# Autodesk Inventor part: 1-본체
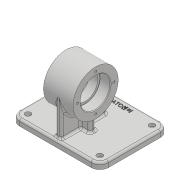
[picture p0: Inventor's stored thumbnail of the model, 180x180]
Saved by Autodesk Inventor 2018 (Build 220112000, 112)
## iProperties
Created: 2019-09
Part Number: 1-본체
Material: 일반
Document SubType Name: Modeling
Designer: USER
Density: 1 g/cm^3
Appearance: 기본값
Author: USER
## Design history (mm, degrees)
sketch "스케치1"
  geometry: L1 (-63, -49)-(63, -49); L2 (63, -49)-(63, 49); L3 (63, 49)-(-63, 49); L4 (-63, 49)-(-63, -49); L5 (-63, -49)-(63, 49); L6 (63, -49)-(-63, 49); 1 further point
  constraints: 12 end point, 2 midpoint, 2 parallel, 1 horizontal, 1 perpendicular
  dimensions: "d0" = 126 distance of L2.end L3.end; "d1" = 98 distance of L1.end L2.end
extrude "돌출1" new body sketch "스케치1" distance "d2" = 9; taper "d3" = 0 deg
sketch "스케치2"
  geometry: L1 (-49, 0)-(-49, 9) reference; L2 (49, 0)-(-49, 0) reference; C1 r 32 at (-13, 59); 1 further point
  constraints: 1 centre point
  dimensions: "d4" = 36 distance from line of L1 C1.centre; "d5" = 64 diameter of C1; "d6" = 59 distance from line of L2 C1.centre
extrude "돌출2" join sketch "스케치2" stored distance "d7" = 42; taper "d8" = 0 deg
sketch "스케치3"
  geometry: L1 (-45, 59)-(19, 59); L2 (19, 59)-(19, 0); L3 (19, 0)-(-45, 0); L4 (-45, 0)-(-45, 59); 2 further points
  constraints: 8 end point, 2 parallel, 1 horizontal, 1 horizontal alignment, 1 perpendicular, 1 other
  dimensions: "d9" = 64 distance between parallel lines of L2 L4; "d10" = 59 distance between parallel lines of L3 L1
extrude "돌출3" join sketch "스케치3" stored distance "d11" = 8; taper "d12" = 0 deg
sketch "스케치4"
  geometry: L1 (49, 0)-(-49, 0) reference; L2 (-17, 59)-(-9, 59); L3 (-9, 59)-(-9, 0); L4 (-9, 0)-(-17, 0); L5 (-17, 0)-(-17, 59); L6 (-49, 0)-(-49, 9) reference; L7 (-49, 9)-(-45, 9) reference; L8 (-45, 9)-(-45, 59) reference; L9 (19, 59)-(19, 9) reference; L10 (19, 9)-(49, 9) reference; L11 (49, 9)-(49, 0) reference; L12 (49, 0)-(-49, 0) reference; L13 (-49, 0)-(-49, 9) reference; L14 (-49, 9)-(-45, 9) reference; L15 (-45, 9)-(-45, 59) reference; L16 (19, 59)-(19, 9) reference; L17 (19, 9)-(49, 9) reference; L18 (49, 9)-(49, 0) reference; L19 (49, 0)-(-49, 0) reference; A1 r 32 centre (-13, 59) between (19, 59) and (-45, 59) reference; A2 r 32 centre (-13, 59) between (19, 59) and (-45, 59) reference; 1 further point
  constraints: 8 end point, 2 parallel, 1 horizontal, 1 perpendicular, 1 point on line
  dimensions: "d13" = 8 distance between parallel lines of L3 L5; "d14" = 59 distance between parallel lines of L1 L2; "d15" = 4 distance from line of L3 A1.centre
extrude "돌출4" join sketch "스케치4" stored distance "d16" = 34; taper "d17" = 0 deg
sketch "스케치5"
  geometry: C1 r 32 at (0, 0) reference; 2 further points
  constraints: 1 coincident
hole "구멍1" sketch "스케치5" at (0, 0) diameter "d18" = 36; stored, may be unused: countersink angle "d22" = 90 deg, drill point angle "d24" = 118 deg; dims "d19" = 6, "d20" = 42, "d21" = 15, "d23" = 36
node "작업 평면1"
sketch "스케치6" dims "d25" = 52
  geometry: A1 r 32 centre (0, 0) between (-31.749, -4) and (0, -32) reference; 3 further points
  constraints: 1 coincident, 1 horizontal alignment, 2 other
hole "구멍2" sketch "스케치6" at (26, 0) diameter "d26" = 3.242; stored, may be unused: countersink angle "d30" = 90 deg, drill point angle "d32" = 118 deg; dims "d27" = 8, "d28" = 42, "d29" = 15, "d31" = 10
sketch "스케치7"
  geometry: L1 (4, -9)-(17, -9) reference; L2 (17, -9)-(17, -17) reference; L3 (17, -17)-(4, -17) reference; L4 (4, -17)-(4, -45) reference; L5 (4, -45)-(-4, -45) reference; L6 (-4, -45)-(-4, -17) reference; L7 (-4, -17)-(-17, -17) reference; L8 (-17, -17)-(-17, -9) reference; L9 (-17, -9)-(-4, -9) reference; L10 (-4, -9)-(-4, 19) reference; L11 (-4, 19)-(4, 19) reference; L12 (4, 19)-(4, -9) reference; L13 (-63, -49)-(-63, 49) reference; L14 (-63, 49)-(63, 49) reference; L15 (63, 49)-(63, -49) reference; L16 (63, -49)-(-63, -49) reference; 5 further points
  dimensions: "d38" = 102 distance of point (-51, 37) point (51, 37); "d39" = 51 horizontal distance of point (0, 0) point (-51, 37) (= 0.5 x d38); "d40" = 102 distance of point (51, -37) point (-51, -37) (= d38); "d41" = 51 horizontal distance of point (0, 0) point (-51, -37) (= d39); "d42" = 74 distance of point (-51, -37) point (-51, 37); "d43" = 37 vertical distance of point (0, 0) point (-51, 37) (= 0.5 x d42)
hole "구멍3" sketch "스케치7" at (-51, 37), (51, 37), (51, -37), (-51, -37) diameter "d44" = 4.5; stored, may be unused: countersink angle "d48" = 90 deg, drill point angle "d50" = 118 deg; dims "d45" = 8, "d46" = 8, "d47" = 4.4, "d49" = 10
fillet "모깎기1" dims "d51" = 12
fillet "모깎기2" dims "d52" = 3
fillet "모깎기3" dims "d53" = 3
fillet "모깎기4" dims "d54" = 3
chamfer "모따기1" distance "d55" = 1; stored, may be unused: second distance "d56" = 2, angle "d57" = 45 deg
fillet "모깎기5" dims "d58" = 0.3
node "작업 평면2"
sketch "스케치8"
  geometry: L1 (63, -37)-(63, 37) reference; L2 (51, 49)-(-51, 49) reference; 2 further points
  constraints: 1 other
  dimensions: "d60" = 63 distance from line of L1 point (0, 39); "d61" = 10 distance from line of L2 point (0, 39)
feature "엠보싱1" sketch "스케치8" dims "d0" = 126, "d1" = 98, "d11" = 8, "d62" = 0.5, "d63" = 0
node "솔리드1"
mirror "미러1"
pattern_circular "원형 패턴1" dims angle "d34" = 360 deg
mirror "미러2"
node "절단 모서리 투영1"
node "절단 모서리 투영2"
node "절단 모서리 투영3"
other parameters: "d59" = 7.25
